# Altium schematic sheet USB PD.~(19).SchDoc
size A3; SheetNumber: 5; SheetTotal: 5
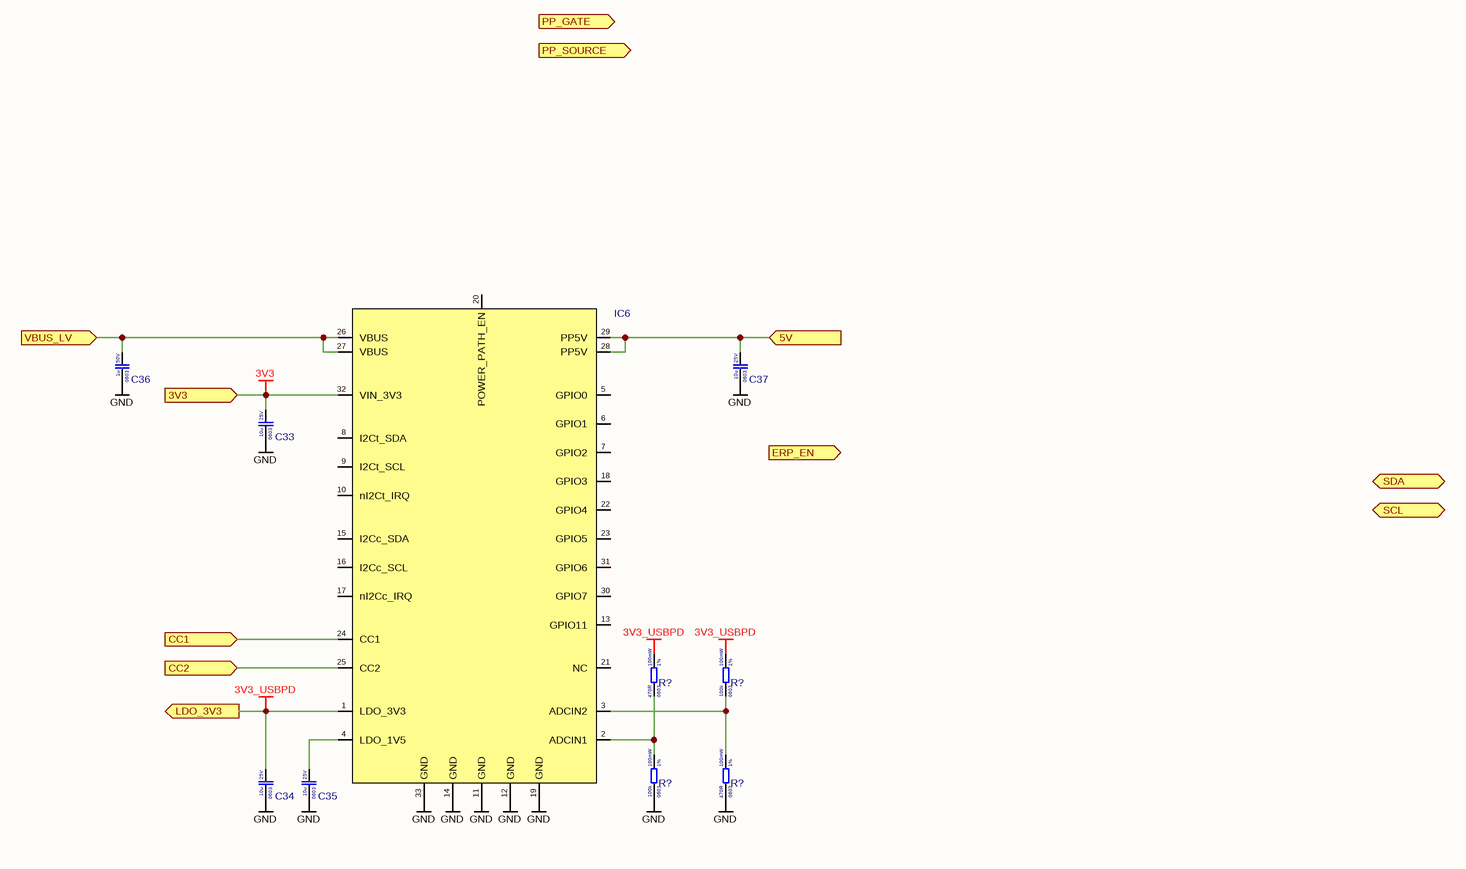
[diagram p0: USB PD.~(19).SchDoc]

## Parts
(Parts that share a designator on the sheet are numbered #1, #2 ... from top to bottom, then left to right.)
C33  Voltage Rating: 25V  Case Code (Imperial): 0603  Capacitance: 10u  [CAP 0603]  (hidden comment: CL10A106MA8NRNC)
C34  Voltage Rating: 25V  Case Code (Imperial): 0603  Capacitance: 10u  [CAP 0603]  (hidden comment: CL10A106MA8NRNC)
C35  Voltage Rating: 25V  Case Code (Imperial): 0603  Capacitance: 10u  [CAP 0603]  (hidden comment: CL10A106MA8NRNC)
C36  Voltage Rating: 50V  Case Code (Imperial): 0603  Capacitance: 1u  [CAP 0603]  (hidden comment: CL10A105KB8NNNC)
C37  Voltage Rating: 25V  Case Code (Imperial): 0603  Capacitance: 10u  [CAP 0603]  (hidden comment: CL10A106MA8NRNC)
IC6  TPS26750SRSMR  [VQFN (32) 4x4]  (value not drawn)
R?#1  Resistance Tolerance: 1%  Resistance: 470R  Power Rating: 100mW  Case Code (Imperial): 0603  [RES_0603]  (hidden comment: 0603WAF4700T5E)
R?#2  Resistance Tolerance: 1%  Resistance: 100k  Power Rating: 100mW  Case Code (Imperial): 0603  [RES_0603]  (hidden comment: 0603WAF1003T5E)
R?#3  Resistance Tolerance: 1%  Resistance: 100k  Power Rating: 100mW  Case Code (Imperial): 0603  [RES_0603]  (hidden comment: 0603WAF1003T5E)
R?#4  Resistance Tolerance: 1%  Resistance: 470R  Power Rating: 100mW  Case Code (Imperial): 0603  [RES_0603]  (hidden comment: 0603WAF4700T5E)

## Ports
3V3 (in, see Arhitecture[4B], Power distribution[5D]), 5V (in, see Arhitecture[4B], Power distribution[5C]), CC1 (in, see Arhitecture[3B]), CC2 (in, see Arhitecture[3B]), ERP_EN (in, see Arhitecture[3B]), LDO_3V3 (out, see Arhitecture[3B]), PP_GATE (out, see Arhitecture[4B]), PP_SOURCE (out, see Arhitecture[4B]), SCL (bidir, see Arhitecture[4B], Charger[3C]), SDA (bidir, see Arhitecture[4B], Charger[3C]), VBUS_LV (in, see Arhitecture[3B])

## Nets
3V3: C33.2 IC6.32(VIN_3V3) ; port 3V3
3V3_USBPD: C34.2 IC6.1(LDO_3V3) R?#1.2 R?#2.2 ; port LDO_3V3
GND: C33.1 C34.1 C35.1 C36.1 C37.1 IC6.11(GND) IC6.12(GND) IC6.14(GND) IC6.19(GND) IC6.33(GND) R?#3.1 R?#4.1
5V: C37.2 IC6.28(PP5V) IC6.29(PP5V) ; port 5V
CC1: IC6.24(CC1) ; port CC1
CC2: IC6.25(CC2) ; port CC2
VBUS_LV: C36.2 IC6.26(VBUS) IC6.27(VBUS) ; port VBUS_LV
NetC35_2: C35.2 IC6.4(LDO_1V5)
NetIC6_2: IC6.2(ADCIN1) R?#1.1 R?#3.2
NetIC6_3: IC6.3(ADCIN2) R?#2.1 R?#4.2

Not connected (* = marked no-connect by the designer): IC6 5(GPIO0) 6(GPIO1) 7(GPIO2) 8(I2Ct_SDA) 9(I2Ct_SCL) 10(nI2Ct_IRQ) 13(GPIO11) 15(I2Cc_SDA) 16(I2Cc_SCL) 17(nI2Cc_IRQ) 18(GPIO3) 20(POWER_PATH_EN) 21(NC) 22(GPIO4) 23(GPIO5) 30(GPIO7) 31(GPIO6)

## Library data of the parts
C33-C35 C37 = CL10A106MA8NRNC: Cap 10uF 25V 0603 X5R; Manufacturer: Samsung
C36 = CL10A105KB8NNNC: Cap 1uF 50V 0603 X5R; Manufacturer: Samsung
IC6 = TPS26750SRSMR: USB PD IC EPR 240W; Manufacturer: Texas Instruments
R?#1 R?#4 = 0603WAF4700T5E: Res 470R 0603 1% 100mW 75V; Manufacturer: Uni-Royal
R?#2 R?#3 = 0603WAF1003T5E: Res 100k 0603 1% 100mW 75V; Manufacturer: Uni-Royal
